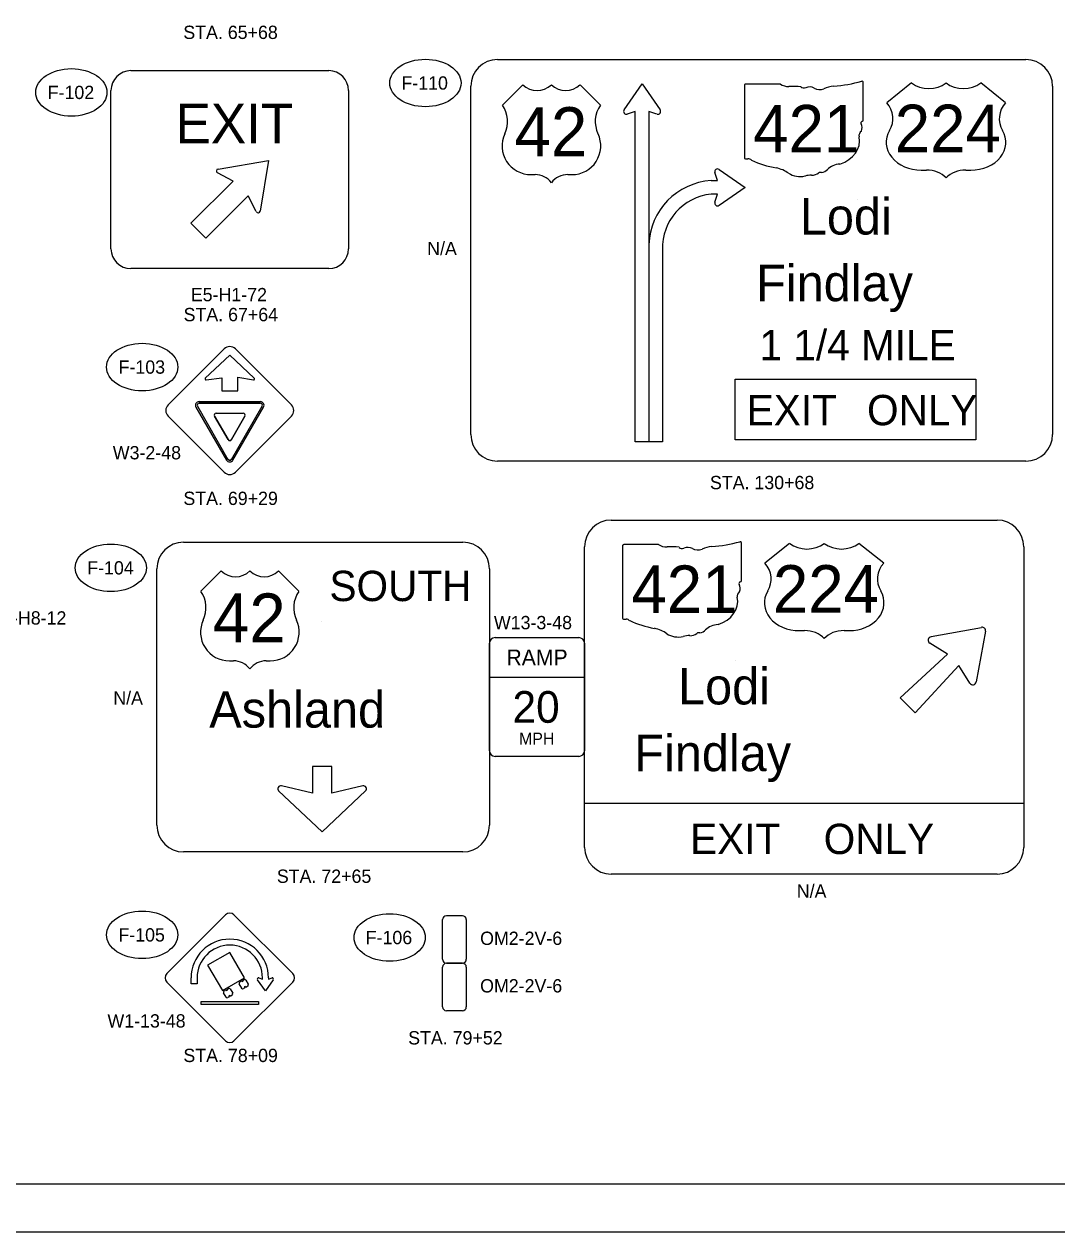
# Model space of a CAD drawing. Extents: x 0 to 34, y 0 to 22.
# Drawn here: x 8.18 to 19.05, y 0 to 12.7 of the extents above; entities that cross this region are included whole.
import ezdxf

# ---------------------------------------------------------------- set-up
doc = ezdxf.new("R2010")
doc.units = 0
for name, color, linetype in [('SH_Border', 7, 'Continuous'), ('SH_Cut_Line', 7, 'Continuous'), ('SH_Data', 7, 'Continuous'), ('SH_Text', 7, 'Continuous'), ('SN_P_Signs', 7, 'Continuous')]:
    doc.layers.add(name, color=color, linetype=linetype)

msp = doc.modelspace()

# ---------------------------------------------------------------- linework, layer by layer
at = {"layer": 'SH_Border'}
msp.add_lwpolyline([(1.5, 21.5), (33.5, 21.5), (33.5, 0.5), (1.5, 0.5)], close=True, dxfattribs=at)
at = {"layer": 'SH_Cut_Line'}
msp.add_lwpolyline([(0, 0), (34, 0), (34, 22), (0, 22)], close=True, dxfattribs=at)
at = {"layer": 'SH_Data'}
msp.add_lwpolyline([(15.667, 8.968), (18.196, 8.968), (18.196, 8.332), (15.667, 8.332)], close=True, dxfattribs=at)
for centre, radius, start, end in [((15.456, 10.361), 0.699, 93.6108, 178.0261), ((15.47, 10.349), 0.57, 95.7978, 181.7619)]:
    msp.add_arc(centre, radius, start, end, dxfattribs=at)
at = {"layer": 'SH_Text'}
for p, q in [((14.758, 10.385), (14.758, 8.309)), ((14.901, 8.309), (14.615, 8.309)), ((14.08, 4.511), (18.702, 4.511))]:
    msp.add_line(p, q, dxfattribs=at)
for centre in [(12.406, 12.085), (8.681, 11.986), (9.426, 9.097), (9.096, 6.985), (9.426, 3.124), (12.03, 3.096)]:
    msp.add_ellipse(centre, major_axis=(0.375, 0), ratio=0.666667, dxfattribs=at)
at = {"layer": 'SN_P_Signs'}
for p, q in [((16.141, 12.072), (15.775, 12.072)), ((17.013, 11.694), (17.013, 12.091)), ((17.52, 12.086), (17.26, 11.878)), ((18.51, 11.878), (18.249, 12.086)), ((13.431, 12.067), (13.216, 11.852)), ((14.247, 11.852), (14.033, 12.067)), ((15.763, 12.059), (15.763, 11.3)), ((17.012, 11.694), (17.013, 11.694)), ((10.225, 11.18), (10.756, 11.27)), ((9.939, 10.609), (10.383, 11.054)), ((10.383, 11.054), (10.219, 11.14)), ((13.517, 11.122), (13.56, 11.122)), ((13.904, 11.122), (13.947, 11.122)), ((17.624, 11.169), (17.677, 11.169)), ((18.093, 11.169), (18.145, 11.169)), ((10.54, 10.897), (10.096, 10.452)), ((10.627, 10.732), (10.54, 10.897)), ((16.952, 10.857), (16.952, 10.857)), ((10.627, 10.732), (10.627, 10.732)), ((10.096, 10.452), (9.939, 10.609)), ((14.901, 10.331), (14.901, 8.309)), ((10.348, 9.223), (10.09, 8.981)), ((10.605, 8.981), (10.348, 9.223)), ((10.099, 8.962), (10.264, 8.983)), ((10.264, 8.983), (10.264, 8.848)), ((10.431, 8.848), (10.431, 8.99)), ((10.431, 8.99), (10.596, 8.963)), ((10.264, 8.848), (10.431, 8.848)), ((9.992, 8.676), (10.314, 8.117)), ((10.007, 8.685), (10.329, 8.126)), ((10.025, 8.734), (10.67, 8.734)), ((10.025, 8.716), (10.67, 8.716)), ((10.366, 8.126), (10.688, 8.685)), ((10.381, 8.117), (10.703, 8.676)), ((10.187, 8.581), (10.33, 8.334)), ((10.205, 8.612), (10.49, 8.612)), ((10.366, 8.334), (10.508, 8.581)), ((15.731, 6.85), (15.731, 7.247)), ((16.238, 7.242), (15.978, 7.034)), ((17.228, 7.034), (16.967, 7.242)), ((14.481, 7.216), (14.481, 6.457)), ((14.859, 7.229), (14.493, 7.229)), ((10.258, 6.952), (10.044, 6.738)), ((11.075, 6.738), (10.86, 6.952)), ((15.73, 6.85), (15.731, 6.85)), ((11.318, 6.423), (11.318, 6.423)), ((17.726, 6.261), (18.258, 6.359)), ((13.14, 6.251), (14.02, 6.251)), ((16.342, 6.326), (16.395, 6.326)), ((16.811, 6.326), (16.863, 6.326)), ((18.301, 6.317), (18.202, 5.785)), ((13.08, 5.061), (13.08, 6.191)), ((14.08, 6.191), (14.08, 5.061)), ((17.898, 6.078), (17.713, 6.193)), ((10.344, 6.007), (10.387, 6.007)), ((10.731, 6.007), (10.774, 6.007)), ((15.67, 6.013), (15.67, 6.013)), ((17.4, 5.619), (17.898, 6.078)), ((18.019, 5.956), (17.561, 5.458)), ((18.134, 5.772), (18.019, 5.956)), ((13.08, 5.834), (14.08, 5.834)), ((17.561, 5.458), (17.4, 5.619)), ((14.02, 5.001), (13.14, 5.001)), ((11.421, 4.895), (11.217, 4.895)), ((11.217, 4.895), (11.217, 4.614)), ((11.421, 4.614), (11.421, 4.895)), ((10.862, 4.638), (11.319, 4.208)), ((11.217, 4.614), (10.891, 4.691)), ((11.319, 4.208), (11.776, 4.638)), ((11.747, 4.691), (11.421, 4.614)), ((9.941, 2.608), (9.941, 2.672)), ((10.003, 2.672), (10.003, 2.608)), ((10.654, 2.671), (10.692, 2.659)), ((10.692, 2.659), (10.692, 2.672)), ((10.755, 2.672), (10.755, 2.659)), ((10.755, 2.659), (10.793, 2.671)), ((10.003, 2.608), (9.941, 2.608)), ((10.723, 2.534), (10.641, 2.652)), ((10.806, 2.652), (10.723, 2.534)), ((10.046, 2.424), (10.649, 2.424)), ((10.046, 2.392), (10.046, 2.424)), ((10.649, 2.424), (10.649, 2.392)), ((10.649, 2.392), (10.046, 2.392))]:
    msp.add_line(p, q, dxfattribs=at)
for points in [[(13.165, 12.332), (18.724, 12.332)], [(9.306, 12.215), (11.389, 12.215)], [(14.497, 11.803), (14.686, 12.076), (14.875, 11.803)], [(9.098, 10.34), (9.098, 12.007)], [(11.598, 12.007), (11.598, 10.34)], [(12.884, 8.388), (12.884, 12.051)], [(19.005, 12.051), (19.005, 8.388)], [(14.615, 8.309), (14.615, 11.786), (14.53, 11.758)], [(14.843, 11.758), (14.758, 11.786), (14.758, 10.385)], [(10.756, 11.27), (10.756, 11.27), (10.666, 10.738)], [(15.412, 11.058), (15.479, 11.058), (15.452, 11.143)], [(15.496, 11.176), (15.77, 10.987), (15.496, 10.798)], [(15.452, 10.83), (15.479, 10.915), (15.412, 10.915)], [(11.389, 10.132), (9.306, 10.132)], [(9.699, 8.699), (10.289, 9.288)], [(10.407, 9.288), (10.996, 8.699)], [(10.007, 8.685), (10.329, 8.126)], [(10.67, 8.716), (10.025, 8.716)], [(10.366, 8.126), (10.688, 8.685)], [(10.289, 7.991), (9.699, 8.581)], [(10.33, 8.334), (10.187, 8.581)], [(10.205, 8.612), (10.49, 8.612)], [(10.508, 8.581), (10.366, 8.334)], [(10.996, 8.581), (10.407, 7.991)], [(18.724, 8.107), (13.165, 8.107)], [(14.362, 7.488), (18.421, 7.488)], [(9.862, 7.255), (12.799, 7.255)], [(14.08, 4.044), (14.08, 7.207)], [(18.702, 7.207), (18.702, 4.044)], [(9.58, 4.277), (9.58, 6.974)], [(13.08, 6.974), (13.08, 4.277)], [(12.799, 3.996), (9.862, 3.996)], [(18.421, 3.763), (14.362, 3.763)], [(10.303, 3.335), (9.685, 2.716)], [(11.011, 2.716), (10.392, 3.335)], [(12.628, 3.326), (12.795, 3.326)], [(12.586, 2.867), (12.586, 3.284)], [(12.836, 3.284), (12.836, 2.867)], [(12.795, 2.826), (12.628, 2.826)], [(12.628, 2.826), (12.795, 2.826)], [(12.586, 2.367), (12.586, 2.784)], [(12.836, 2.784), (12.836, 2.367)], [(9.685, 2.628), (10.303, 2.009)], [(10.323, 2.554), (10.334, 2.56)], [(10.352, 2.555), (10.379, 2.51)], [(10.392, 2.009), (11.011, 2.628)], [(10.473, 2.564), (10.447, 2.609)], [(10.452, 2.628), (10.462, 2.634)], [(10.487, 2.648), (10.498, 2.655)], [(10.503, 2.565), (10.492, 2.559)], [(10.516, 2.649), (10.542, 2.604)], [(10.537, 2.585), (10.527, 2.579)], [(10.309, 2.469), (10.283, 2.515)], [(10.288, 2.534), (10.299, 2.54)], [(10.34, 2.471), (10.328, 2.464)], [(10.373, 2.49), (10.363, 2.484)], [(12.795, 2.326), (12.628, 2.326)]]:
    msp.add_lwpolyline(points, dxfattribs=at)
msp.add_lwpolyline([(10.27, 2.538), (10.503, 2.672), (10.348, 2.94), (10.115, 2.805)], close=True, dxfattribs=at)
for centre, radius, start, end in [((13.165, 12.051), 0.281, 90, 180), ((18.724, 12.051), 0.281, 0, 90), ((9.306, 12.007), 0.208, 90, 180), ((11.389, 12.007), 0.208, 0, 90), ((13.581, 12.221), 0.215, 225.573, 314.427), ((13.882, 12.221), 0.215, 225.573, 314.427), ((12.97, 11.68), 0.301, 334.5471, 35.0009), ((14.494, 11.68), 0.301, 144.9991, 205.4529), ((14.521, 11.786), 0.029, 145.3614, 287.7282), ((14.852, 11.786), 0.029, 252.2718, 34.6386), ((13.514, 11.423), 0.301, 154.8319, 270.6383), ((13.95, 11.423), 0.301, 269.3617, 25.1681), ((15.479, 11.152), 0.029, 55.3614, 197.7282), ((10.228, 11.159), 0.0208, 99.6076, 242.1805), ((13.56, 10.907), 0.215, 36.8699, 90), ((13.904, 10.907), 0.215, 90, 143.1301), ((15.479, 10.822), 0.029, 162.2718, 304.6386), ((10.646, 10.741), 0.0208, 207.8195, 350.3924), ((9.306, 10.34), 0.208, 180, 270), ((11.389, 10.34), 0.208, 270, 0), ((10.348, 9.229), 0.0833, 45, 135), ((10.098, 8.973), 0.0106, 133.2891, 277.1751), ((10.598, 8.973), 0.0106, 260.4249, 46.7109), ((9.758, 8.64), 0.0833, 135, 225), ((10.025, 8.695), 0.0383, 90, 210), ((10.025, 8.695), 0.0211, 90, 210), ((10.025, 8.695), 0.0211, 90, 210), ((10.67, 8.695), 0.0383, 330, 90), ((10.67, 8.695), 0.0211, 330, 90), ((10.67, 8.695), 0.0211, 330, 90), ((10.937, 8.64), 0.0833, 315, 45), ((10.205, 8.591), 0.0208, 90, 210), ((10.205, 8.591), 0.0208, 90, 210), ((10.49, 8.591), 0.0208, 330, 90), ((10.49, 8.591), 0.0208, 330, 90), ((13.165, 8.388), 0.281, 180, 270), ((18.724, 8.388), 0.281, 270, 0), ((10.348, 8.344), 0.0208, 210, 330), ((10.348, 8.344), 0.0208, 210, 330), ((10.348, 8.137), 0.0383, 210, 330), ((10.348, 8.137), 0.0211, 210, 330), ((10.348, 8.137), 0.0211, 210, 330), ((10.348, 8.05), 0.0833, 225, 315), ((14.362, 7.207), 0.281, 90, 180), ((18.421, 7.207), 0.281, 0, 90), ((9.862, 6.974), 0.281, 90, 180), ((12.799, 6.974), 0.281, 0, 90), ((10.409, 7.106), 0.215, 225.573, 314.427), ((10.71, 7.106), 0.215, 225.573, 314.427), ((9.797, 6.565), 0.301, 334.5471, 35.0009), ((11.321, 6.565), 0.301, 144.9991, 205.4529), ((10.341, 6.308), 0.301, 154.8319, 270.6383), ((10.777, 6.308), 0.301, 269.3617, 25.1681), ((18.264, 6.323), 0.0371, 350.9064, 99.0936), ((13.14, 6.191), 0.06, 90, 180), ((14.02, 6.191), 0.06, 0, 90), ((17.733, 6.224), 0.0371, 100.5029, 237.9762), ((10.387, 5.792), 0.215, 36.8699, 90), ((10.731, 5.792), 0.215, 90, 143.1301), ((18.166, 5.792), 0.0371, 212.0238, 349.4971), ((13.14, 5.061), 0.06, 180, 270), ((14.02, 5.061), 0.06, 270, 0), ((10.884, 4.661), 0.0313, 76.7561, 226.7357), ((11.754, 4.661), 0.0313, 313.2643, 103.2439), ((9.862, 4.277), 0.281, 180, 270), ((12.799, 4.277), 0.281, 270, 0), ((14.362, 4.044), 0.281, 180, 270), ((18.421, 4.044), 0.281, 270, 0), ((10.348, 3.291), 0.0625, 45, 135), ((12.628, 3.284), 0.0417, 90, 180), ((12.795, 3.284), 0.0417, 0, 90), ((10.348, 2.672), 0.407, 0, 180), ((10.348, 2.672), 0.344, 0, 180), ((12.628, 2.867), 0.0417, 180, 270), ((12.628, 2.784), 0.0417, 90, 180), ((12.795, 2.867), 0.0417, 270, 0), ((12.795, 2.784), 0.0417, 0, 90), ((9.729, 2.672), 0.0625, 135, 225), ((10.65, 2.659), 0.0122, 72.3622, 215.0792), ((10.796, 2.659), 0.0122, 324.9208, 107.6378), ((10.966, 2.672), 0.0625, 315, 45), ((10.306, 2.528), 0.014, 30, 120), ((10.33, 2.542), 0.014, 120, 210), ((10.34, 2.548), 0.014, 30, 120), ((10.459, 2.616), 0.014, 120, 210), ((10.469, 2.622), 0.014, 30, 120), ((10.485, 2.571), 0.014, 210, 300), ((10.494, 2.636), 0.014, 120, 210), ((10.504, 2.642), 0.014, 30, 120), ((10.495, 2.577), 0.014, 300, 30), ((10.52, 2.591), 0.014, 210, 300), ((10.53, 2.597), 0.014, 300, 30), ((10.295, 2.522), 0.014, 120, 210), ((10.321, 2.476), 0.014, 210, 300), ((10.332, 2.482), 0.014, 300, 30), ((10.356, 2.496), 0.014, 210, 300), ((10.366, 2.503), 0.014, 300, 30), ((12.628, 2.367), 0.0417, 180, 270), ((12.795, 2.367), 0.0417, 270, 0), ((10.348, 2.053), 0.0625, 225, 315)]:
    msp.add_arc(centre, radius, start, end, dxfattribs=at)
for centre, major_axis, start_param, end_param in [((15.777, 12.061), (0.0145, 0), 1.712693, 3.28349), ((16.228, 12.16), (0.14, 0), 4.042523, 4.731795), ((16.567, 13.107), (1.326, 0), 4.814394, 5.042369), ((16.999, 12.093), (0.0139, 0), 6.141152, 7.989035), ((17.703, 12.235), (-0.26, 0), 0.795399, 2.346194), ((18.067, 12.235), (-0.26, 0), 0.795399, 2.346194), ((16.275, 11.646), (0.504, 0), 1.404758, 1.657858), ((16.389, 12.065), (0.0405, 0), 3.836095, 5.185415), ((16.449, 11.977), (0.0842, 0), 0.950623, 2.079405), ((16.557, 12.097), (0.101, 0), 4.081561, 5.145723), ((16.736, 11.84), (0.267, 0), 1.699011, 2.107814), ((16.961, 11.71), (0.365, 0), 5.838949, 6.894067), ((18.809, 11.71), (-0.365, 0), 5.672304, 6.727422), ((16.998, 11.693), (0.0149, 0), 5.05454, 6.418171), ((17.062, 11.528), (0.0941, 0), 2.387724, 3.262537), ((17.009, 11.665), (0.0215, 0), 1.883978, 3.671073), ((16.872, 11.615), (0.129, 0), 5.934695, 6.695948), ((17.62, 11.461), (0.365, 0), 2.702327, 4.723529), ((18.149, 11.461), (-0.365, 0), 1.559657, 3.580859), ((16.642, 11.477), (0.332, 0), 5.101752, 6.440018), ((15.777, 11.299), (0.0146, 0), 3.00124, 4.508301), ((15.779, 11.376), (0.111, 0), 4.665946, 4.897461), ((15.802, 11.256), (0.0402, 0), 0.519207, 1.627899), ((16.31, 11.938), (0.957, 0), 4.195997, 4.488961), ((16.024, 10.959), (0.3, 0), 0.823519, 1.323587), ((16.781, 11.087), (0.182, 0), 1.647645, 2.488434), ((16.348, 11.253), (0.19, 0), 4.026481, 4.996735), ((16.458, 10.99), (0.156, 0), 1.495662, 1.94098), ((16.472, 11.196), (0.101, 0), 4.691044, 5.507374), ((16.563, 11.122), (0.0285, 0), 1.147584, 2.315152), ((16.551, 11.227), (0.107, 0), 4.937069, 5.64225), ((17.677, 10.961), (-0.26, 0), 3.785094, 4.712389), ((18.093, 10.961), (-0.26, 0), 4.712389, 5.639684), ((15.285, 8.263), (1.326, 0), 4.814394, 5.042369), ((15.717, 7.249), (0.0139, 0), 6.141152, 7.989035), ((16.421, 7.391), (-0.26, 0), 0.795399, 2.346194), ((16.785, 7.391), (-0.26, 0), 0.795399, 2.346194), ((14.495, 7.217), (0.0145, 0), 1.712693, 3.28349), ((14.946, 7.317), (0.14, 0), 4.042523, 4.731795), ((14.993, 6.803), (0.504, 0), 1.404758, 1.657858), ((15.107, 7.221), (0.0405, 0), 3.836095, 5.185415), ((15.167, 7.133), (0.0842, 0), 0.950623, 2.079405), ((15.275, 7.254), (0.101, 0), 4.081561, 5.145723), ((15.454, 6.997), (0.267, 0), 1.699011, 2.107814), ((15.679, 6.867), (0.365, 0), 5.838949, 6.894067), ((17.527, 6.867), (-0.365, 0), 5.672304, 6.727422), ((15.78, 6.684), (0.0941, 0), 2.387724, 3.262537), ((15.727, 6.821), (0.0215, 0), 1.883978, 3.671073), ((15.59, 6.771), (0.129, 0), 5.934695, 6.695948), ((15.716, 6.849), (0.0149, 0), 5.05454, 6.418171), ((16.338, 6.617), (0.365, 0), 2.702327, 4.723529), ((16.867, 6.617), (-0.365, 0), 1.559657, 3.580859), ((15.36, 6.634), (0.332, 0), 5.101752, 6.440018), ((14.495, 6.455), (0.0146, 0), 3.00124, 4.508301), ((14.497, 6.533), (0.111, 0), 4.665946, 4.897461), ((14.52, 6.413), (0.0402, 0), 0.519207, 1.627899), ((15.028, 7.095), (0.957, 0), 4.195997, 4.488961), ((15.499, 6.243), (0.182, 0), 1.647645, 2.488434), ((14.742, 6.116), (0.3, 0), 0.823519, 1.323587), ((15.066, 6.409), (0.19, 0), 4.026481, 4.996735), ((15.176, 6.147), (0.156, 0), 1.495662, 1.94098), ((15.19, 6.352), (0.101, 0), 4.691044, 5.507374), ((15.281, 6.279), (0.0285, 0), 1.147584, 2.315152), ((15.269, 6.383), (0.107, 0), 4.937069, 5.64225), ((16.395, 6.117), (-0.26, 0), 3.785094, 4.712389), ((16.811, 6.117), (-0.26, 0), 4.712389, 5.639684)]:
    msp.add_ellipse(centre, major_axis=major_axis, ratio=0.8, start_param=start_param, end_param=end_param, dxfattribs=at)

# ---------------------------------------------------------------- texts
at = {"layer": 'SH_Text'}
for s, p in [('STA. 65+68', (9.859, 12.548)), ('F-110', (12.154, 12.015)), ('F-102', (8.432, 11.916)), ('N/A', (12.425, 10.274)), ('E5-H1-72', (9.938, 9.789)), ('STA. 67+64', (9.862, 9.579)), ('F-103', (9.178, 9.027)), ('W3-2-48', (9.117, 8.126)), ('STA. 130+68', (15.4, 7.812)), ('STA. 69+29', (9.86, 7.646)), ('F-104', (8.848, 6.915)), ('D10-H8-12', (7.713, 6.388)), ('W13-3-48', (13.127, 6.339)), ('N/A', (9.122, 5.546)), ('STA. 72+65', (10.843, 3.671)), ('N/A', (16.314, 3.514)), ('F-105', (9.176, 3.054)), ('F-106', (11.778, 3.026)), ('OM2-2V-6', (12.982, 3.018)), ('OM2-2V-6', (12.982, 2.518)), ('W1-13-48', (9.061, 2.149)), ('STA. 79+52', (12.225, 1.971)), ('STA. 78+09', (9.86, 1.786))]:
    msp.add_text(s, height=0.14, dxfattribs=at).set_placement(p)
at = {"layer": 'SN_P_Signs'}
for s, height, p in [('EXIT', 0.4167, (9.777, 11.451)), ('42', 0.5156, (13.343, 11.315)), ('421', 0.5, (15.856, 11.354)), ('224', 0.5, (17.345, 11.357)), ('Lodi', 0.3828, (16.346, 10.491)), ('Findlay', 0.3828, (15.886, 9.79)), ('1 1/4 MILE', 0.319, (15.922, 9.168)), ('EXIT', 0.319, (15.787, 8.485)), ('ONLY', 0.319, (17.053, 8.485)), ('421', 0.5, (14.574, 6.51)), ('224', 0.5, (16.063, 6.513)), ('SOUTH', 0.319, (11.397, 6.635)), ('42', 0.5156, (10.17, 6.2)), ('RAMP', 0.1667, (13.259, 5.959)), ('Lodi', 0.3828, (15.064, 5.548)), ('Ashland', 0.3828, (10.132, 5.304)), ('20', 0.3333, (13.323, 5.355)), ('MPH', 0.125, (13.392, 5.126)), ('Findlay', 0.3828, (14.604, 4.846)), ('EXIT', 0.319, (15.191, 3.974)), ('ONLY', 0.319, (16.597, 3.974))]:
    msp.add_text(s, height=height, dxfattribs=at).set_placement(p)

doc.saveas('drawing.dxf')
